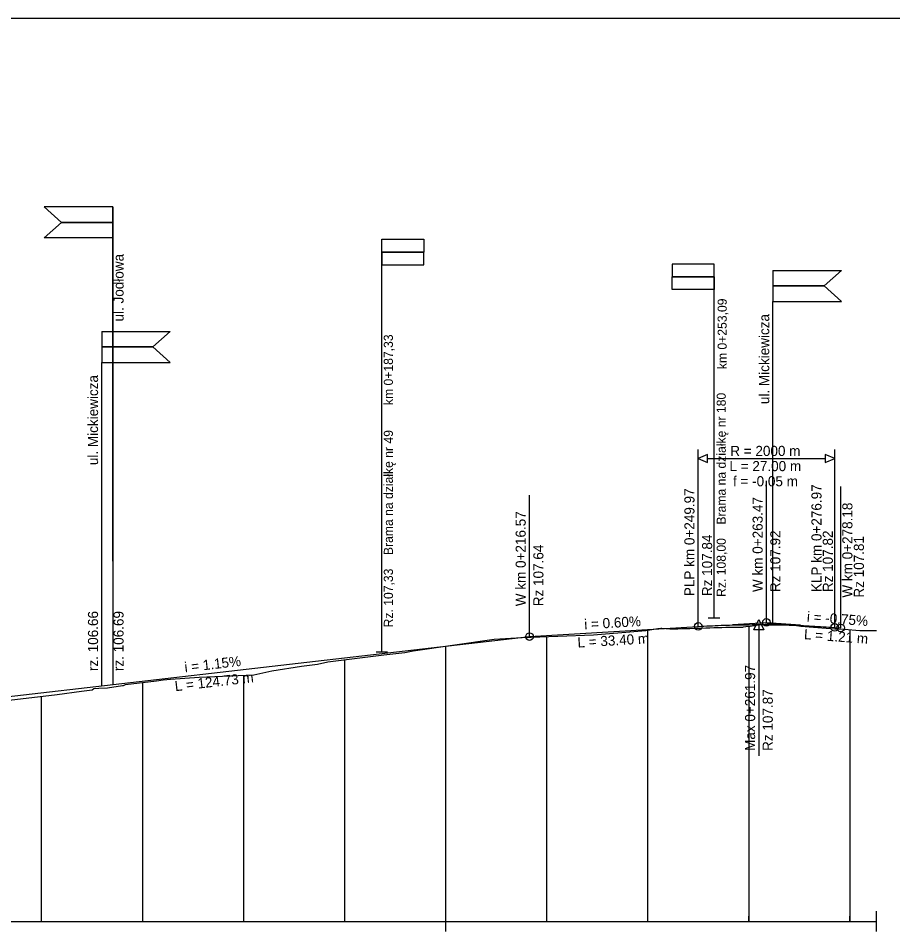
# Model space of a CAD drawing. Extents: x 7481207 to 7481727, y 5776531 to 5776815.
# Drawn here: x 7481380.5 to 7481553.6, y 5776633.9 to 5776814.9 of the extents above; entities that cross this region are included whole.
import ezdxf

# ---------------------------------------------------------------- set-up
doc = ezdxf.new("R2010")
doc.units = 0
for name, color, linetype in [('d_p_opisy_drog', 7, 'Continuous'), ('opis niwelety', 7, 'Continuous'), ('prof_niweleta', 7, 'Continuous'), ('prof_odniesienie', 7, 'Continuous'), ('prof_os', 7, 'Continuous'), ('ramka', 7, 'Continuous'), ('teren', 7, 'Continuous'), ('zjazdy lewe', 7, 'Continuous'), ('zjazdy prawe', 7, 'Continuous')]:
    doc.layers.add(name, color=color, linetype=linetype)

msp = doc.modelspace()

# ---------------------------------------------------------------- linework, layer by layer
at = {"layer": 'd_p_opisy_drog'}
for p, q in [((7481399.21, 5776777.55), (7481385.67, 5776777.55)), ((7481399.21, 5776771.42), (7481399.21, 5776777.55)), ((7481399.21, 5776771.42), (7481399.21, 5776777.55)), ((7481399.21, 5776777.55), (7481399.21, 5776683)), ((7481399.21, 5776774.47), (7481389.11, 5776774.47)), ((7481399.21, 5776771.42), (7481385.67, 5776771.42)), ((7481399.21, 5776707.41), (7481399.21, 5776771.42)), ((7481529.91, 5776764.96), (7481529.91, 5776758.84)), ((7481529.91, 5776764.96), (7481543.45, 5776764.96)), ((7481529.91, 5776764.96), (7481529.91, 5776758.84)), ((7481529.91, 5776761.92), (7481540.01, 5776761.92)), ((7481529.91, 5776758.84), (7481543.45, 5776758.84)), ((7481529.91, 5776694.83), (7481529.91, 5776758.84)), ((7481397.06, 5776752.88), (7481397.06, 5776746.76)), ((7481397.06, 5776752.88), (7481410.6, 5776752.88)), ((7481397.06, 5776752.88), (7481397.06, 5776746.76)), ((7481397.06, 5776749.84), (7481407.16, 5776749.84)), ((7481397.06, 5776746.76), (7481410.6, 5776746.76)), ((7481397.06, 5776682.75), (7481397.06, 5776746.76))]:
    msp.add_line(p, q, dxfattribs=at)
for points in [[(7481385.67, 5776777.55), (7481389.11, 5776774.47), (7481385.67, 5776771.42)], [(7481399.21, 5776774.47), (7481399.21, 5776777.55), (7481385.67, 5776777.55), (7481389.11, 5776774.47), (7481399.21, 5776774.47)], [(7481543.45, 5776758.84), (7481540.01, 5776761.92), (7481543.45, 5776764.96)], [(7481529.91, 5776761.92), (7481529.91, 5776758.84), (7481543.45, 5776758.84), (7481540.01, 5776761.92), (7481529.91, 5776761.92)], [(7481410.6, 5776746.76), (7481407.16, 5776749.84), (7481410.6, 5776752.88)], [(7481397.06, 5776749.84), (7481397.06, 5776746.76), (7481410.6, 5776746.76), (7481407.16, 5776749.84), (7481397.06, 5776749.84)]]:
    msp.add_lwpolyline(points, dxfattribs=at)
at = {"layer": 'prof_niweleta'}
for p, q in [((7481515.12, 5776694.49), (7481515.12, 5776729.49)), ((7481542.12, 5776694.29), (7481542.12, 5776729.49)), ((7481515.12, 5776694.49), (7481515.12, 5776726.49)), ((7481542.12, 5776695.29), (7481542.12, 5776727.29)), ((7481528.62, 5776695.3), (7481528.62, 5776723.3)), ((7481543.33, 5776694.2), (7481543.33, 5776722.2)), ((7481481.72, 5776692.49), (7481481.72, 5776720.49)), ((7481481.72, 5776692.49), (7481515.12, 5776694.49)), ((7481521.87, 5776694.89), (7481528.62, 5776695.3)), ((7481527.12, 5776694.85), (7481527.12, 5776668.85)), ((7481528.62, 5776695.3), (7481535.37, 5776694.79)), ((7481542.12, 5776694.29), (7481542.12, 5776695.29)), ((7481542.12, 5776694.29), (7481543.33, 5776694.2)), ((7481357, 5776678.14), (7481481.72, 5776692.49))]:
    msp.add_line(p, q, dxfattribs=at)
for points in [[(7481515.12, 5776727.74), (7481516.96, 5776726.97), (7481516.96, 5776728.5)], [(7481542.12, 5776727.74), (7481540.27, 5776728.5), (7481540.27, 5776726.97)], [(7481527.12, 5776695.85), (7481528.12, 5776693.85), (7481526.12, 5776693.85)]]:
    msp.add_lwpolyline(points, close=True, dxfattribs=at)
for points in [[(7481516.96, 5776727.74), (7481540.27, 5776727.74)], [(7481515.12, 5776694.49), (7481515.68, 5776694.52), (7481516.24, 5776694.55), (7481516.8, 5776694.58), (7481517.37, 5776694.61), (7481517.93, 5776694.64), (7481518.49, 5776694.66), (7481519.05, 5776694.69), (7481519.62, 5776694.71), (7481520.18, 5776694.73), (7481520.74, 5776694.75), (7481521.3, 5776694.77), (7481521.87, 5776694.78), (7481522.43, 5776694.79), (7481522.99, 5776694.81), (7481523.55, 5776694.82), (7481524.12, 5776694.83), (7481524.68, 5776694.83), (7481525.24, 5776694.84), (7481525.8, 5776694.85), (7481526.37, 5776694.85), (7481526.93, 5776694.85), (7481527.49, 5776694.85), (7481528.05, 5776694.85), (7481529.18, 5776694.84), (7481529.74, 5776694.83), (7481530.3, 5776694.82), (7481530.87, 5776694.81), (7481531.43, 5776694.8), (7481531.99, 5776694.79), (7481532.55, 5776694.78), (7481533.12, 5776694.76), (7481533.68, 5776694.74), (7481534.24, 5776694.72), (7481534.8, 5776694.7), (7481535.37, 5776694.68), (7481535.93, 5776694.66), (7481536.49, 5776694.63), (7481537.05, 5776694.6), (7481537.62, 5776694.57), (7481538.18, 5776694.54), (7481538.74, 5776694.51), (7481539.3, 5776694.48), (7481539.87, 5776694.44), (7481540.43, 5776694.41), (7481540.99, 5776694.37), (7481541.55, 5776694.33), (7481542.12, 5776694.29)]]:
    msp.add_lwpolyline(points, dxfattribs=at)
for centre in [(7481528.62, 5776695.3), (7481515.12, 5776694.49), (7481542.12, 5776694.29), (7481543.33, 5776694.2), (7481481.72, 5776692.49)]:
    msp.add_circle(centre, 0.75, dxfattribs=at)
at = {"layer": 'prof_odniesienie'}
for p, q in [((7481525.15, 5776694.54), (7481525.15, 5776636.1)), ((7481545.15, 5776693.85), (7481545.15, 5776636.1)), ((7481485.15, 5776636.1), (7481485.15, 5776692.47)), ((7481505.15, 5776636.1), (7481505.15, 5776693.75)), ((7481465.15, 5776636.1), (7481465.15, 5776690.57)), ((7481445.15, 5776636.1), (7481445.15, 5776687.9)), ((7481425.15, 5776636.1), (7481425.15, 5776684.85)), ((7481405.15, 5776636.1), (7481405.15, 5776683.41)), ((7481385.15, 5776636.1), (7481385.15, 5776680.66))]:
    msp.add_line(p, q, dxfattribs=at)
at = {"layer": 'prof_os'}
for p, q in [((7481465.15, 5776634.1), (7481465.15, 5776638.1)), ((7481550.38, 5776634.1), (7481550.38, 5776638.1)), ((7481265.15, 5776636.1), (7481550.38, 5776636.1)), ((7481385.15, 5776636.1), (7481385.15, 5776637.1)), ((7481405.15, 5776636.1), (7481405.15, 5776637.1)), ((7481425.15, 5776636.1), (7481425.15, 5776637.1)), ((7481445.15, 5776636.1), (7481445.15, 5776637.1)), ((7481485.15, 5776636.1), (7481485.15, 5776637.1)), ((7481505.15, 5776636.1), (7481505.15, 5776637.1)), ((7481525.15, 5776636.1), (7481525.15, 5776637.1)), ((7481545.15, 5776636.1), (7481545.15, 5776637.1))]:
    msp.add_line(p, q, dxfattribs=at)
at = {"layer": 'ramka'}
for points in [[(7481207.45, 5776814.89), (7481727.02, 5776814.89), (7481727.02, 5776530.89), (7481207.45, 5776530.89)], [(7481207.45, 5776814.89), (7481567.02, 5776814.89), (7481567.02, 5776530.89), (7481207.45, 5776530.89)]]:
    msp.add_lwpolyline(points, close=True, dxfattribs=at)
at = {"layer": 'teren'}
msp.add_lwpolyline([(7481378.73, 5776679.87), (7481388.23, 5776681.04), (7481393.06, 5776681.65), (7481395.14, 5776681.97), (7481395.45, 5776682.22), (7481396.48, 5776682.28), (7481398.16, 5776682.35), (7481401.13, 5776682.8), (7481401.35, 5776682.8), (7481401.75, 5776682.99), (7481407.89, 5776683.75), (7481409.23, 5776683.91), (7481410.68, 5776684.02), (7481416.3, 5776684.46), (7481427.14, 5776684.94), (7481430.72, 5776685.71), (7481436.59, 5776686.62), (7481439.73, 5776687.04), (7481441.83, 5776687.48), (7481452.88, 5776688.88), (7481457.04, 5776689.36), (7481458.72, 5776689.64), (7481474.75, 5776691.95), (7481480.29, 5776692.27), (7481494.4, 5776692.83), (7481503.15, 5776693.55), (7481503.95, 5776693.62), (7481504.74, 5776693.69), (7481504.74, 5776693.69), (7481505.53, 5776693.81), (7481506.32, 5776693.93), (7481507.11, 5776694.07), (7481507.71, 5776694.18), (7481507.9, 5776694.16), (7481508.69, 5776694.09), (7481509.48, 5776694.02), (7481509.9, 5776694), (7481510.27, 5776694.01), (7481511.06, 5776694.03), (7481511.85, 5776694.06), (7481512.64, 5776694.08), (7481513.43, 5776694.11), (7481514.23, 5776694.13), (7481515.02, 5776694.16), (7481515.81, 5776694.18), (7481516.6, 5776694.21), (7481517.39, 5776694.24), (7481518.18, 5776694.26), (7481518.97, 5776694.29), (7481519.6, 5776694.31), (7481519.76, 5776694.31), (7481520.55, 5776694.32), (7481521.34, 5776694.34), (7481522.13, 5776694.35), (7481522.92, 5776694.36), (7481523.71, 5776694.37), (7481523.93, 5776694.37), (7481524.07, 5776694.41), (7481524.55, 5776694.47), (7481525.39, 5776694.57), (7481526.22, 5776694.68), (7481527.06, 5776694.79), (7481527.9, 5776694.9), (7481528.73, 5776695.01), (7481529.09, 5776695.05), (7481529.48, 5776695.1), (7481529.57, 5776695.07), (7481529.82, 5776695), (7481530.41, 5776694.97), (7481531.24, 5776694.93), (7481531.29, 5776694.93), (7481531.46, 5776694.9), (7481532.08, 5776694.88), (7481532.92, 5776694.85), (7481532.97, 5776694.85), (7481533.75, 5776694.75), (7481534.59, 5776694.66), (7481535.43, 5776694.57), (7481536.26, 5776694.48), (7481537.1, 5776694.4), (7481537.94, 5776694.33), (7481538.77, 5776694.26), (7481539.61, 5776694.2), (7481540.45, 5776694.15), (7481541.28, 5776694.1), (7481542.12, 5776694.05), (7481542.82, 5776694.02), (7481542.96, 5776694.01), (7481543.98, 5776693.95), (7481547.13, 5776693.69), (7481550.38, 5776693.67)], dxfattribs=at)
at = {"layer": 'zjazdy lewe'}
for p, q in [((7481518.24, 5776696.1), (7481518.24, 5776766.22)), ((7481518.24, 5776763.69), (7481509.94, 5776763.69)), ((7481518.24, 5776763.69), (7481509.94, 5776763.69)), ((7481519.36, 5776696.1), (7481517.11, 5776696.1))]:
    msp.add_line(p, q, dxfattribs=at)
for points in [[(7481518.24, 5776763.69), (7481518.24, 5776766.22), (7481509.94, 5776766.22), (7481509.94, 5776763.69)], [(7481518.24, 5776763.69), (7481518.24, 5776761.19), (7481509.94, 5776761.19), (7481509.94, 5776763.69)]]:
    msp.add_lwpolyline(points, close=True, dxfattribs=at)
at = {"layer": 'zjazdy prawe'}
for p, q in [((7481452.48, 5776689.39), (7481452.48, 5776771.14)), ((7481452.48, 5776768.61), (7481460.77, 5776768.61)), ((7481452.48, 5776768.61), (7481460.77, 5776768.61)), ((7481453.6, 5776689.39), (7481451.35, 5776689.39))]:
    msp.add_line(p, q, dxfattribs=at)
for points in [[(7481452.48, 5776768.61), (7481452.48, 5776771.14), (7481460.77, 5776771.14), (7481460.77, 5776768.61)], [(7481452.48, 5776768.61), (7481452.48, 5776766.11), (7481460.77, 5776766.11), (7481460.77, 5776768.61)]]:
    msp.add_lwpolyline(points, close=True, dxfattribs=at)

# ---------------------------------------------------------------- texts
at = {"layer": 'd_p_opisy_drog'}
for s, p in [('km 0+253,09', (7481520.75, 5776745.43)), ('km 0+187,33', (7481454.68, 5776738.32)), ('Rz. 108,00    Brama na działkę nr 180', (7481520.56, 5776700.34)), ('Rz. 107,33    Brama na działkę nr 49', (7481454.68, 5776694.3))]:
    msp.add_text(s, height=1.8, rotation=90, dxfattribs=at).set_placement(p)
at = {"layer": 'opis niwelety'}
for s, p in [('ul. Jodłowa', (7481401.37, 5776754.86)), ('ul. Mickiewicza', (7481529.17, 5776738.51)), ('ul. Mickiewicza', (7481396.32, 5776726.43)), ('rz. 106.66', (7481396.32, 5776685.65)), ('rz. 106.69', (7481401.37, 5776685.65))]:
    msp.add_text(s, height=2, rotation=90, dxfattribs=at).set_placement(p)
at = {"layer": 'prof_niweleta'}
for s, p in [('R = 2000 m', (7481521.45, 5776728.24)), ('L = 27.00 m', (7481521.29, 5776725.24)), ('f = -0.05 m', (7481521.99, 5776722.24))]:
    msp.add_text(s, height=2, dxfattribs=at).set_placement(p)
for s, rotation, p in [('PLP km 0+249.97', 90, (7481514.37, 5776700.49)), ('KLP km 0+276.97', 90, (7481539.52, 5776701.29)), ('W km 0+263.47', 90, (7481527.87, 5776701.3)), ('W km 0+278.18', 90, (7481545.63, 5776700.2)), ('W km 0+216.57', 90, (7481480.97, 5776698.49)), ('Rz 107.84', 90, (7481517.87, 5776700.49)), ('Rz 107.92', 90, (7481531.37, 5776701.3)), ('Rz 107.82', 90, (7481541.76, 5776701.29)), ('Rz 107.81', 90, (7481547.91, 5776700.2)), ('Rz 107.64', 90, (7481484.47, 5776698.49)), ('i = -0.75%', 355.7108, (7481536.56, 5776695.46)), ('i = 0.60%', 3.4336, (7481492.61, 5776693.89)), ('L = 1.21 m', 355.7108, (7481535.99, 5776691.99)), ('L = 33.40 m', 3.4336, (7481491.27, 5776690.3)), ('i = 1.15%', 6.5602, (7481413.54, 5776685.4)), ('Max 0+261.97', 90, (7481526.37, 5776669.85)), ('L = 124.73 m', 6.5602, (7481411.62, 5776681.66)), ('Rz 107.87', 90, (7481529.87, 5776669.85))]:
    msp.add_text(s, height=2, rotation=rotation, dxfattribs=at).set_placement(p)

doc.saveas('drawing.dxf')
